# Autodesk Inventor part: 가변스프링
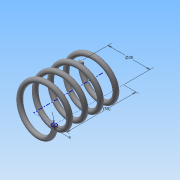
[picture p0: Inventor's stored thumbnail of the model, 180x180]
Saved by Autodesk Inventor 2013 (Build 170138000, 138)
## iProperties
Created: 2015-03
Part Number: 가변스프링
Material: 강철, 탄소
Document SubType Name: Modeling
Designer: Administrator
Density: 7.87 g/cm^3
Mass: 48.2733 g
Surface Area: 62.0009 cm^2
Volume: 6.13384 cm^3
Author: Administrator
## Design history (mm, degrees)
sketch "스케치1"
  geometry: L1 (0, 0)-(17.5, 0); L2 (17.5, 0)-(17.5, 43.5); L3 (17.5, 43.5)-(0, 43.5); L4 (0, 43.5)-(0, 0); C1 r 2 at (17.5, 0)
  constraints: 8 end point, 2 parallel, 1 centre point, 1 coincident, 1 horizontal, 1 perpendicular
  dimensions: "d0" = 35 diameter of L2 L4; "d2" = 43.5 distance of L1.end L2.end (derived); "d3" = 4 diameter of C1
feature "코일1" sketch "스케치1" pitch "d4" = 10; turns "d6" = 4.5; dims "d5" = 43.5 (= d2), "d7" = 0, angle "d8" = 90 deg, angle "d9" = 90 deg, "d10" = 0, "d11" = 0
node "작업 평면1"
sketch "스케치2"
  geometry: L1 (-19.5, 0)-(-15.5, 0) reference; 1 further point
  constraints: 1 horizontal alignment
extrude "돌출1" cut sketch "스케치2" stored distance "d13" = 10; taper "d14" = 0 deg
node "작업 평면2"
sketch "스케치3"
  geometry: L1 (-19.5, 0)-(-15.5, 0) reference; 1 further point
  constraints: 1 horizontal alignment
extrude "돌출2" cut sketch "스케치3" stored distance "d16" = 10; taper "d17" = 0 deg
node "솔리드1"
node "절단 모서리 투영1"
node "절단 모서리 투영2"
other parameters: "d12" = 0, "d15" = -43.5 (= -d2)
